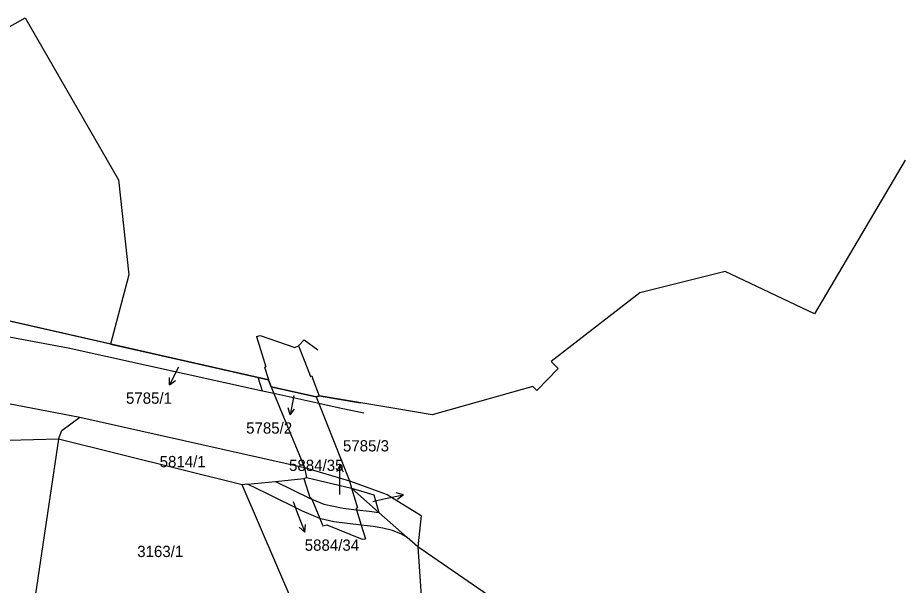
# Model space of a CAD drawing. Extents: x -738085 to -734306, y -1122197 to -1119753.
# Drawn here: x -734440.5 to -734306.5, y -1120128.8 to -1120043.1 of the extents above; entities that cross this region are included whole.
import ezdxf

# ---------------------------------------------------------------- set-up
doc = ezdxf.new("R2010")
doc.units = 0
for name, color, linetype in [('Hranice parcel', 7, 'Continuous'), ('Parcelní čísla', 7, 'Continuous'), ('Pop  PČ popisy', 7, 'Continuous'), ('Vnitřní kresba', 7, 'Continuous'), ('Vrstva 53', 7, 'Continuous')]:
    doc.layers.add(name, color=color, linetype=linetype)

msp = doc.modelspace()

# ---------------------------------------------------------------- linework, layer by layer
at = {"layer": 'Hranice parcel'}
for p, q in [((-734426.51, -1120092.35), (-734445.03, -1120088.16)), ((-734403.56, -1120099.44), (-734404.24, -1120097.39)), ((-734406.64, -1120113.59), (-734434.38, -1120106.7)), ((-734405.82, -1120113.51), (-734406.64, -1120113.59)), ((-734398.18, -1120133.23), (-734406.64, -1120113.59)), ((-734405.82, -1120113.51), (-734401.61, -1120113.08)), ((-734390.15, -1120114.08), (-734385.98, -1120117.77)), ((-734385.98, -1120117.77), (-734381.7, -1120121.54)), ((-734379.59, -1120118.25), (-734380.11, -1120122.95)), ((-734380.11, -1120122.95), (-734381.7, -1120121.54)), ((-734380.11, -1120122.95), (-734379.27, -1120135.19)), ((-734364.71, -1120133.53), (-734380.11, -1120122.95))]:
    msp.add_line(p, q, dxfattribs=at)
for points in [[(-734446.28, -1120045.36), (-734445.48, -1120046.51), (-734439.4, -1120043.1), (-734425.34, -1120067.55), (-734423.76, -1120081.88), (-734426.51, -1120092.35)], [(-734572.48, -1120072.28), (-734567.68, -1120072.61), (-734497.04, -1120089.52), (-734478.31, -1120092.85), (-734456.87, -1120097.64), (-734450.98, -1120099.09), (-734441.92, -1120101.33), (-734431.18, -1120103.41), (-734397.21, -1120110.97), (-734390.44, -1120112.99), (-734384.75, -1120115.04), (-734379.59, -1120118.25)], [(-734403.56, -1120099.44), (-734432.9, -1120092.95), (-734451.59, -1120089.48), (-734457.2, -1120088.44), (-734457.58, -1120088.34), (-734476.2, -1120083.49), (-734493.47, -1120079.65), (-734529.14, -1120071.48)], [(-734426.51, -1120092.35), (-734420.23, -1120093.77), (-734404.24, -1120097.39)], [(-734404.24, -1120097.39), (-734402.65, -1120097.75), (-734402.26, -1120098.83), (-734395.48, -1120100.32), (-734395.03, -1120100.19), (-734388.79, -1120101.23)], [(-734388.27, -1120102.8), (-734391.71, -1120102.07), (-734395.08, -1120101.32), (-734401.85, -1120099.82), (-734402.11, -1120099.76), (-734403.56, -1120099.44)], [(-734434.38, -1120106.7), (-734441.91, -1120106.9), (-734443.58, -1120106.95)], [(-734434.38, -1120106.7), (-734438.42, -1120133.78), (-734438.25, -1120134.95)], [(-734401.61, -1120113.08), (-734397.35, -1120112.65), (-734396.92, -1120112.5), (-734390.15, -1120114.08)], [(-734381.7, -1120121.54), (-734382.57, -1120121.07), (-734383.94, -1120120.5), (-734385.4, -1120120.14), (-734386.88, -1120119.89), (-734388.65, -1120119.68), (-734392.82, -1120119.18), (-734394.77, -1120118.74), (-734394.91, -1120118.68), (-734397.54, -1120117.58), (-734402.92, -1120114.93), (-734405.82, -1120113.51)], [(-734401.61, -1120113.08), (-734396.39, -1120115.64), (-734396.12, -1120115.77), (-734394.33, -1120116.52), (-734391.39, -1120117.11), (-734389.35, -1120117.35), (-734387.43, -1120117.57), (-734385.98, -1120117.77)], [(-734390.15, -1120114.08), (-734386.76, -1120115.11), (-734385.98, -1120117.77)]]:
    msp.add_lwpolyline(points, dxfattribs=at)
at = {"layer": 'Pop  PČ popisy'}
for p, q in [((-734416.28, -1120095.83), (-734417.6, -1120098.53)), ((-734417.6, -1120098.53), (-734417.61, -1120097.41)), ((-734417.6, -1120098.53), (-734416.71, -1120097.85)), ((-734398.84, -1120100.1), (-734399.41, -1120103.05)), ((-734399.41, -1120103.05), (-734399.71, -1120101.97)), ((-734399.41, -1120103.05), (-734398.73, -1120102.16)), ((-734391.88, -1120110.65), (-734392.38, -1120111.65)), ((-734391.88, -1120113.65), (-734391.88, -1120110.65)), ((-734391.88, -1120110.65), (-734391.38, -1120111.65)), ((-734391.88, -1120115.08), (-734391.88, -1120113.65)), ((-734385.22, -1120115.72), (-734382.29, -1120115.1)), ((-734382.29, -1120115.1), (-734383.37, -1120114.81)), ((-734382.29, -1120115.1), (-734383.16, -1120115.79)), ((-734398.96, -1120116.09), (-734398.26, -1120117.92)), ((-734386.92, -1120116.09), (-734385.22, -1120115.72)), ((-734398.26, -1120117.92), (-734397.19, -1120120.72)), ((-734397.19, -1120120.72), (-734397.08, -1120119.61)), ((-734397.19, -1120120.72), (-734398.01, -1120119.97))]:
    msp.add_line(p, q, dxfattribs=at)
at = {"layer": 'Vnitřní kresba'}
for p, q in [((-734404.47, -1120091.19), (-734403.93, -1120091.06)), ((-734404.47, -1120091.19), (-734403.05, -1120095.77)), ((-734403.93, -1120091.06), (-734398.71, -1120092.85)), ((-734398.71, -1120092.85), (-734398.13, -1120092.63)), ((-734398.13, -1120092.63), (-734397.28, -1120091.71)), ((-734398.13, -1120092.63), (-734397.19, -1120095.02)), ((-734397.28, -1120091.71), (-734395.22, -1120093.24)), ((-734397.19, -1120095.02), (-734396.32, -1120097.24)), ((-734403.26, -1120095.84), (-734403.05, -1120095.77)), ((-734403.26, -1120095.84), (-734402.77, -1120097.38)), ((-734402.77, -1120097.38), (-734402.65, -1120097.75)), ((-734396.32, -1120097.24), (-734396.12, -1120097.17)), ((-734396.12, -1120097.17), (-734395.95, -1120097.63)), ((-734395.95, -1120097.63), (-734395.03, -1120100.19)), ((-734402.26, -1120098.83), (-734401.85, -1120099.82)), ((-734401.85, -1120099.82), (-734397.21, -1120110.97)), ((-734395.48, -1120100.32), (-734395.08, -1120101.32)), ((-734395.08, -1120101.32), (-734390.44, -1120112.99)), ((-734433.9, -1120105.4), (-734431.18, -1120103.41)), ((-734434.38, -1120106.7), (-734433.9, -1120105.4)), ((-734397.21, -1120110.97), (-734396.92, -1120112.5)), ((-734397.35, -1120112.65), (-734396.39, -1120115.64)), ((-734390.44, -1120112.99), (-734390.15, -1120114.08)), ((-734390.15, -1120114.08), (-734389.23, -1120117.07)), ((-734396.39, -1120115.64), (-734396.2, -1120115.57)), ((-734396.2, -1120115.57), (-734396.12, -1120115.77)), ((-734396.12, -1120115.77), (-734394.91, -1120118.68)), ((-734389.42, -1120117.13), (-734389.23, -1120117.07)), ((-734389.42, -1120117.13), (-734389.35, -1120117.35)), ((-734389.35, -1120117.35), (-734388.65, -1120119.68)), ((-734394.91, -1120118.68), (-734394.46, -1120119.77)), ((-734394.46, -1120119.77), (-734393.87, -1120119.64)), ((-734393.87, -1120119.64), (-734388.54, -1120121.8)), ((-734388.65, -1120119.68), (-734388.03, -1120121.73)), ((-734388.54, -1120121.8), (-734388.03, -1120121.73))]:
    msp.add_line(p, q, dxfattribs=at)
at = {"layer": 'Vrstva 53'}
msp.add_lwpolyline([(-734306.5, -1120064.6), (-734320.21, -1120087.78), (-734333.67, -1120081.4), (-734346.58, -1120084.61), (-734359.95, -1120095), (-734358.89, -1120096.03), (-734362.15, -1120099.35), (-734362.58, -1120098.93), (-734362.76, -1120098.74), (-734377.92, -1120103.05), (-734383.28, -1120102.15), (-734395.03, -1120100.19), (-734395.48, -1120100.32), (-734402.26, -1120098.83), (-734402.65, -1120097.75), (-734404.24, -1120097.39), (-734420.23, -1120093.77), (-734445.03, -1120088.16)], dxfattribs=at)

# ---------------------------------------------------------------- texts
at = {"layer": 'Parcelní čísla'}
for s, p in [('5785/1', (-734424.19, -1120101.36)), ('5785/2', (-734406.04, -1120105.87)), ('5785/3', (-734391.42, -1120108.56)), ('5814/1', (-734419.1, -1120110.94)), ('5884/35', (-734399.56, -1120111.5)), ('5884/34', (-734397.19, -1120123.55)), ('3163/1', (-734422.49, -1120124.5))]:
    msp.add_text(s, height=1.7, dxfattribs=at).set_placement(p)

doc.saveas('drawing.dxf')
